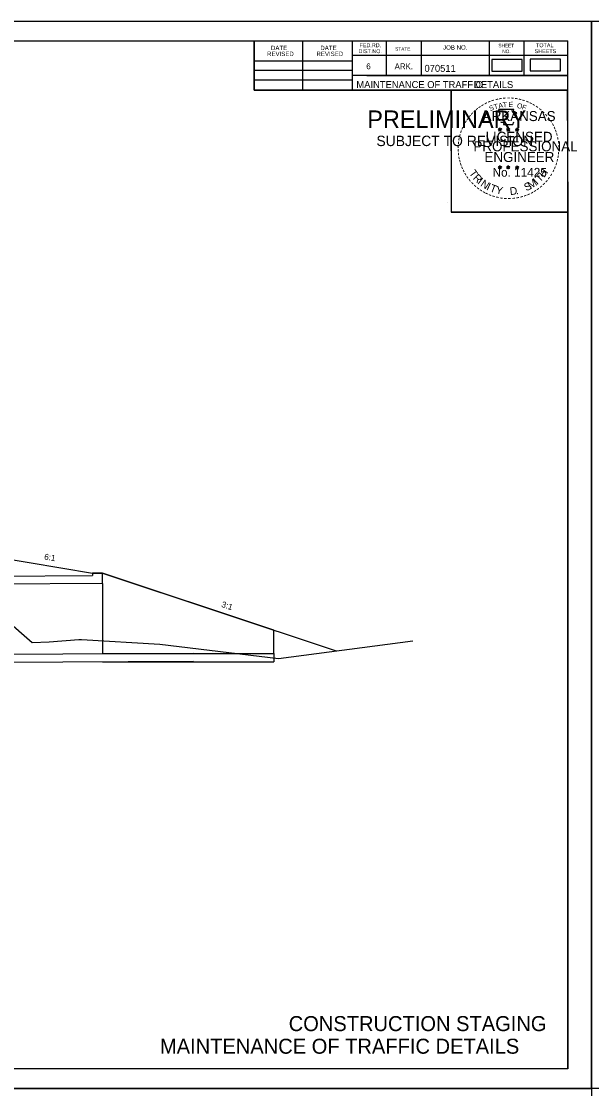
# Model space of a CAD drawing. Extents: x 1398460 to 1408037, y 380768 to 383968.
# Drawn here: x 1401763 to 1402332, y 382901 to 383968 of the extents above; entities that cross this region are included whole.
import ezdxf

# ---------------------------------------------------------------- set-up
doc = ezdxf.new("R2010")
doc.units = 0
for name, color, linetype in [('R_Border', 7, 'Continuous'), ('R_Border PE', 7, 'Continuous'), ('R_Border Prem', 7, 'Continuous'), ('R_Dimension', 7, 'Continuous'), ('R_Draft', 7, 'Continuous'), ('R_Exist Surface', 7, 'Continuous'), ('R_Fin Surface', 7, 'Continuous'), ('R_No Plot', 7, 'Continuous'), ('R_Water', 7, 'Continuous')]:
    doc.layers.add(name, color=color, linetype=linetype)

msp = doc.modelspace()

# ---------------------------------------------------------------- linework, layer by layer
at = {"layer": 'R_Border'}
for p, q in [((1400727.6, 383948.1), (1402308.5, 383948.1)), ((1401995.3, 383898.7), (1401995.3, 383948.1)), ((1402043.7, 383898.7), (1402043.7, 383948.1)), ((1402093, 383948.1), (1402093, 383898.7)), ((1402127.2, 383948.1), (1402127.2, 383913.4)), ((1402161.9, 383948.1), (1402161.9, 383913.4)), ((1402229.8, 383948.1), (1402229.8, 383913.4)), ((1402264.5, 383948.1), (1402264.5, 383913.4)), ((1402308.5, 382920.8), (1402308.5, 383948.1)), ((1402308.5, 383933.4), (1402093, 383933.4)), ((1402308.5, 383933.5), (1402308.5, 383933.5)), ((1401995.3, 383928), (1402093, 383928)), ((1401995.3, 383918.7), (1402093, 383918.7)), ((1402308.5, 383913.4), (1402093, 383913.4)), ((1402107.8, 383913.4), (1402308.5, 383913.4)), ((1401995.3, 383909), (1402093, 383909)), ((1402308.5, 383898.7), (1401995.3, 383898.7)), ((1402308.5, 382920.8), (1400727.6, 382920.8))]:
    msp.add_line(p, q, dxfattribs=at)
at = {"layer": 'R_Border PE'}
for p, q in [((1402238.9, 383860), (1402240.6, 383859.4)), ((1402238.9, 383860), (1402240.2, 383859.8)), ((1402238.9, 383860), (1402240.1, 383859.4)), ((1402239.6, 383857.9), (1402240.6, 383859.4)), ((1402239.6, 383857.9), (1402240.2, 383859.2)), ((1402239.6, 383857.9), (1402240.6, 383859)), ((1402240.6, 383861.3), (1402240.4, 383860)), ((1402240.6, 383859.4), (1402240.6, 383861.3)), ((1402240.6, 383861.3), (1402240.9, 383860)), ((1402242.4, 383860), (1402240.6, 383859.4)), ((1402241.7, 383857.9), (1402240.6, 383859.4)), ((1402241.7, 383857.9), (1402240.6, 383859)), ((1402242.4, 383860), (1402240.9, 383859.7)), ((1402241.7, 383857.9), (1402241, 383859.4)), ((1402242.4, 383860), (1402241.4, 383859.5)), ((1402247.2, 383860), (1402249, 383859.4)), ((1402247.2, 383860), (1402248.5, 383859.8)), ((1402247.2, 383860), (1402248.4, 383859.4)), ((1402247.9, 383857.9), (1402249, 383859.4)), ((1402247.9, 383857.9), (1402248.5, 383859.2)), ((1402247.9, 383857.9), (1402249, 383859)), ((1402249, 383861.3), (1402248.8, 383860)), ((1402249, 383859.4), (1402249, 383861.3)), ((1402249, 383861.3), (1402249.2, 383860)), ((1402250.7, 383860), (1402249, 383859.4)), ((1402250.1, 383857.9), (1402249, 383859.4)), ((1402250.1, 383857.9), (1402249, 383859)), ((1402250.7, 383860), (1402249.3, 383859.7)), ((1402250.1, 383857.9), (1402249.4, 383859.4)), ((1402250.7, 383860), (1402249.7, 383859.5)), ((1402256.1, 383859.9), (1402257.8, 383859.4)), ((1402256.1, 383859.9), (1402257.3, 383859.7)), ((1402256.1, 383859.9), (1402257.2, 383859.3)), ((1402256.7, 383857.9), (1402257.8, 383859.4)), ((1402256.7, 383857.9), (1402257.4, 383859.1)), ((1402256.7, 383857.9), (1402257.8, 383859)), ((1402257.8, 383861.2), (1402257.6, 383859.9)), ((1402257.8, 383859.4), (1402257.8, 383861.2)), ((1402257.8, 383861.2), (1402258.1, 383859.9)), ((1402259.5, 383859.9), (1402257.8, 383859.4)), ((1402258.9, 383857.9), (1402257.8, 383859.4)), ((1402258.9, 383857.9), (1402257.8, 383859)), ((1402259.5, 383859.9), (1402258.1, 383859.7)), ((1402258.9, 383857.9), (1402258.2, 383859.3)), ((1402259.5, 383859.9), (1402258.5, 383859.4)), ((1402238.9, 383822.1), (1402240.6, 383821.6)), ((1402238.9, 383822.1), (1402240.1, 383821.9)), ((1402238.9, 383822.1), (1402240.1, 383821.5)), ((1402239.5, 383820.1), (1402240.6, 383821.6)), ((1402239.5, 383820.1), (1402240.2, 383821.3)), ((1402239.5, 383820.1), (1402240.6, 383821.2)), ((1402240.6, 383823.4), (1402240.4, 383822.1)), ((1402240.6, 383821.6), (1402240.6, 383823.4)), ((1402240.6, 383823.4), (1402240.9, 383822.1)), ((1402242.4, 383822.1), (1402240.6, 383821.6)), ((1402241.7, 383820.1), (1402240.6, 383821.6)), ((1402241.7, 383820.1), (1402240.6, 383821.1)), ((1402242.4, 383822.1), (1402240.9, 383821.9)), ((1402241.7, 383820.1), (1402241, 383821.5)), ((1402242.4, 383822.1), (1402241.3, 383821.6)), ((1402247.2, 383822.1), (1402249, 383821.6)), ((1402247.2, 383822.1), (1402248.5, 383821.9)), ((1402247.2, 383822.1), (1402248.4, 383821.5)), ((1402247.9, 383820.1), (1402249, 383821.6)), ((1402247.9, 383820.1), (1402248.5, 383821.3)), ((1402247.9, 383820.1), (1402249, 383821.2)), ((1402249, 383823.4), (1402248.8, 383822.1)), ((1402249, 383821.6), (1402249, 383823.4)), ((1402249, 383823.4), (1402249.2, 383822.1)), ((1402250.7, 383822.1), (1402249, 383821.6)), ((1402250, 383820.1), (1402249, 383821.6)), ((1402250, 383820.1), (1402249, 383821.1)), ((1402250.7, 383822.1), (1402249.3, 383821.9)), ((1402250, 383820.1), (1402249.3, 383821.5)), ((1402250.7, 383822.1), (1402249.7, 383821.6)), ((1402256.1, 383822.1), (1402257.8, 383821.5)), ((1402256.1, 383822.1), (1402257.3, 383821.8)), ((1402256.1, 383822.1), (1402257.2, 383821.5)), ((1402256.7, 383820), (1402257.8, 383821.5)), ((1402256.7, 383820), (1402257.3, 383821.2)), ((1402256.7, 383820), (1402257.8, 383821.1)), ((1402257.8, 383823.3), (1402257.6, 383822.1)), ((1402257.8, 383821.5), (1402257.8, 383823.3)), ((1402257.8, 383823.3), (1402258, 383822.1)), ((1402259.5, 383822.1), (1402257.8, 383821.5)), ((1402258.9, 383820), (1402257.8, 383821.5)), ((1402258.9, 383820), (1402257.8, 383821.1)), ((1402259.5, 383822.1), (1402258.1, 383821.8)), ((1402258.9, 383820), (1402258.2, 383821.5)), ((1402259.5, 383822.1), (1402258.5, 383821.6))]:
    msp.add_line(p, q, dxfattribs=at)
for points in [[(1402239.1, 383879.4), (1402240.4, 383875.2)], [(1402256.7, 383874.8), (1402257.4, 383876.2), (1402253.9, 383876.1), (1402254.7, 383879.4), (1402239.1, 383879.4)], [(1402240.6, 383861.3), (1402241.7, 383857.9), (1402238.9, 383860), (1402242.4, 383860), (1402239.6, 383857.9), (1402240.6, 383861.3)], [(1402241.6, 383867.3), (1402241.6, 383866.8), (1402244.4, 383866.7), (1402244.1, 383864.4), (1402253.5, 383864.4), (1402254.5, 383867)], [(1402249, 383861.3), (1402250.1, 383857.9), (1402247.2, 383860), (1402250.7, 383860), (1402247.9, 383857.9), (1402249, 383861.3)], [(1402257.8, 383861.2), (1402258.9, 383857.9), (1402256.1, 383859.9), (1402259.5, 383859.9), (1402256.7, 383857.9), (1402257.8, 383861.2)], [(1402240.6, 383823.4), (1402241.7, 383820.1), (1402238.9, 383822.1), (1402242.4, 383822.1), (1402239.5, 383820.1), (1402240.6, 383823.4)], [(1402249, 383823.4), (1402250, 383820.1), (1402247.2, 383822.1), (1402250.7, 383822.1), (1402247.9, 383820.1), (1402249, 383823.4)], [(1402257.8, 383823.3), (1402258.9, 383820), (1402256.1, 383822.1), (1402259.5, 383822.1), (1402256.7, 383820), (1402257.8, 383823.3)]]:
    msp.add_lwpolyline(points, dxfattribs=at)
for centre, radius in [((1402240.6, 383859.4), 0.861), ((1402240.6, 383859.4), 0.723), ((1402240.6, 383859.4), 0.579), ((1402240.6, 383859.4), 0.495), ((1402240.6, 383859.4), 0.374), ((1402240.6, 383859.4), 0.248), ((1402240.6, 383859.4), 0.148), ((1402249, 383859.4), 0.861), ((1402249, 383859.4), 0.723), ((1402249, 383859.4), 0.579), ((1402249, 383859.4), 0.495), ((1402249, 383859.4), 0.374), ((1402249, 383859.4), 0.248), ((1402249, 383859.4), 0.148), ((1402257.8, 383859.4), 0.861), ((1402257.8, 383859.4), 0.723), ((1402257.8, 383859.4), 0.579), ((1402257.8, 383859.4), 0.495), ((1402257.8, 383859.4), 0.374), ((1402257.8, 383859.4), 0.248), ((1402257.8, 383859.4), 0.148), ((1402240.6, 383821.6), 0.861), ((1402240.6, 383821.6), 0.723), ((1402240.6, 383821.6), 0.579), ((1402240.6, 383821.6), 0.495), ((1402240.6, 383821.6), 0.374), ((1402240.6, 383821.6), 0.248), ((1402240.6, 383821.6), 0.148), ((1402249, 383821.6), 0.861), ((1402249, 383821.6), 0.723), ((1402249, 383821.6), 0.579), ((1402249, 383821.6), 0.495), ((1402249, 383821.6), 0.374), ((1402249, 383821.6), 0.248), ((1402249, 383821.6), 0.148), ((1402257.8, 383821.5), 0.861), ((1402257.8, 383821.5), 0.723), ((1402257.8, 383821.5), 0.579), ((1402257.8, 383821.5), 0.495), ((1402257.8, 383821.5), 0.374), ((1402257.8, 383821.5), 0.248), ((1402257.8, 383821.5), 0.148)]:
    msp.add_circle(centre, radius, dxfattribs=at)
at = {"layer": 'R_Dimension'}
for points in [[(1402232.5, 383917.7), (1402262.7, 383917.7), (1402262.7, 383929.3), (1402232.5, 383929.3)], [(1402270.8, 383918.2), (1402301.1, 383918.2), (1402301.1, 383929.8), (1402270.8, 383929.8)]]:
    msp.add_lwpolyline(points, close=True, dxfattribs=at)
at = {"layer": 'R_Exist Surface'}
msp.add_lwpolyline([(1401687, 383422.3), (1401773.4, 383346.7), (1401790.6, 383347.4), (1401820.1, 383349.8), (1401822.6, 383349.9), (1401901, 383345.2), (1402019.4, 383330.7), (1402153.8, 383348.6)], dxfattribs=at)
at = {"layer": 'R_Fin Surface'}
msp.add_line((1401678.9, 383442), (1401833.6, 383416.2), dxfattribs=at)
msp.add_lwpolyline([(1401833.6, 383416.2), (1401843.6, 383416.2), (1402077, 383338.4)], dxfattribs=at)
at = {"layer": 'R_No Plot'}
for p, q in [((1400665.6, 383967.6), (1402332.2, 383967.6)), ((1402188.6, 383786.4), (1402188.6, 383786.4)), ((1400665.6, 382900.9), (1402332.2, 382900.9)), ((1400665.6, 382900.9), (1402332.2, 382900.9))]:
    msp.add_line(p, q, dxfattribs=at)
for points in [[(1400665.5, 383967.6), (1402332.2, 383967.6), (1402332.2, 382900.9), (1400665.5, 382900.9)], [(1402332.2, 383967.6), (1403998.9, 383967.6), (1403998.9, 382900.9), (1402332.2, 382900.9)], [(1401897.2, 383948.1), (1401995.3, 383948.1), (1401995.3, 383898.7), (1402075.8, 383898.7), (1402191.8, 383898.7), (1402191.8, 383777), (1402308.5, 383777), (1402308.5, 382920.8), (1400727.6, 382920.8), (1400727.6, 383948.1)], [(1402191.8, 383898.7), (1402307.9, 383898.7), (1402308.5, 383777), (1402192.4, 383777)], [(1400665.5, 382900.9), (1402332.2, 382900.9), (1402332.2, 381834.2), (1400665.5, 381834.2)]]:
    msp.add_lwpolyline(points, close=True, dxfattribs=at)
at = {"layer": 'R_Water'}
for p, q in [((1401498.9, 383412), (1401833.6, 383413.6)), ((1402014.9, 383359.1), (1401843.6, 383416.2)), ((1401843.6, 383405.6), (1401498.9, 383404)), ((1401843.6, 383405.8), (1401843.6, 383335.8)), ((1402014.9, 383335.8), (1402014.9, 383359.1)), ((1401498.9, 383334), (1401934.7, 383336.1)), ((1401843.6, 383335.8), (1402014.9, 383335.8)), ((1402014.9, 383335.8), (1402014.9, 383327.4)), ((1401934.7, 383327.7), (1401498.9, 383325.7)), ((1401843.6, 383327.4), (1402014.9, 383327.4))]:
    msp.add_line(p, q, dxfattribs=at)
msp.add_lwpolyline([(1401843.6, 383405.8), (1401843.6, 383416.2), (1401833.6, 383416.2), (1401833.6, 383413.7)], dxfattribs=at)

# ---------------------------------------------------------------- texts
at = {"layer": 'R_Border'}
for s, height, p in [('FED.RD.', 3.91, (1402100.4, 383941.7)), ('JOB NO.', 4.4, (1402183.9, 383939.3)), ('SHEET', 3.42, (1402239.1, 383941.7)), ('TOTAL', 3.91, (1402276.7, 383941.7)), ('REVISED', 4.4, (1402008.1, 383932.9)), ('DATE', 4.4, (1402012, 383938.8)), ('REVISED', 4.4, (1402057.4, 383932.9)), ('DATE', 4.4, (1402061.3, 383938.8)), ('DIST.NO.', 3.91, (1402099.4, 383935.8)), ('STATE', 3.42, (1402136, 383938.3)), ('NO.', 3.42, (1402243, 383935.8)), ('SHEETS', 3.91, (1402275.3, 383935.8)), ('6', 5.86, (1402107.2, 383919.7)), ('ARK.', 5.86, (1402135.5, 383919.7)), ('070511', 7, (1402165.3, 383917.1)), ('MAINTENANCE OF TRAFFIC', 7, (1402097.3, 383900.9)), (' DETAILS', 7, (1402212.3, 383900.9)), ('CONSTRUCTION STAGING', 15, (1402029.7, 382958.4)), ('MAINTENANCE OF TRAFFIC DETAILS', 15, (1401901.1, 382935.8))]:
    msp.add_text(s, height=height, dxfattribs=at).set_placement(p)
at = {"layer": 'R_Border PE'}
for s, height, rotation, p in [('-', 8, 13.6302, (1402236.6, 383886.2)), ('-', 8, 10.2193, (1402240, 383887)), ('-', 8, 5.8968, (1402243.6, 383887.6)), ('-', 8, 0.1862, (1402247.5, 383887.9)), ('-', 8, 357.743, (1402251.1, 383887.9)), ('-', 8, 352.1617, (1402254.8, 383887.6)), ('-', 8, 347.2049, (1402258.4, 383887)), ('-', 8, 38.9507, (1402218.2, 383876.4)), ('-', 8, 36.2317, (1402220.6, 383878.3)), ('-', 8, 34.0636, (1402223.5, 383880.2)), ('-', 8, 28.7918, (1402226.5, 383882.1)), ('-', 8, 24.3072, (1402229.7, 383883.7)), ('S', 5, 21.594, (1402230.9, 383877.8)), ('-', 8, 19.1761, (1402232.8, 383885)), ('T', 5, 16.4036, (1402235.4, 383879.4)), ('A', 5, 11.2132, (1402239.6, 383880.7)), ('T', 5, 6.0228, (1402243.8, 383881.5)), ('E', 5, 0.8323, (1402249.3, 383882.1)), ('O', 5, 350.4515, (1402257.4, 383881)), ('F', 5, 340.0707, (1402262.1, 383879.9)), ('-', 8, 342.3362, (1402261.6, 383886.2)), ('-', 8, 337.8551, (1402265.3, 383885.1)), ('-', 8, 334.1211, (1402268.4, 383883.8)), ('-', 8, 329.6409, (1402271.3, 383882.4)), ('-', 8, 325.8627, (1402274.5, 383880.6)), ('-', 8, 320.5297, (1402277.6, 383878.4)), ('-', 8, 54.2325, (1402209.8, 383866.6)), ('-', 8, 50.6142, (1402211.8, 383869.5)), ('-', 8, 48.4231, (1402213.8, 383871.9)), ('-', 8, 42.9622, (1402216.1, 383874.3)), ('-', 8, 315.5786, (1402280.6, 383876)), ('-', 8, 309.8797, (1402283.4, 383873.2)), ('-', 8, 306.6522, (1402286, 383870.2)), ('-', 8, 72.3945, (1402204.2, 383854.7)), ('-', 8, 67.7743, (1402205.3, 383857.9)), ('-', 8, 62.8713, (1402206.6, 383860.9)), ('-', 8, 58.0706, (1402208.1, 383864)), ('-', 7, 303.6753, (1402288.5, 383867.4)), ('-', 8, 299.6684, (1402290.1, 383864.3)), ('-', 8, 294.6628, (1402291.7, 383861.3)), ('-', 8, 290.5728, (1402293, 383858.4)), ('-', 8, 81.2013, (1402202.5, 383847.6)), ('-', 8, 75.461, (1402203.2, 383851.1)), ('-', 8, 285.1233, (1402294.1, 383855.5)), ('-', 8, 280.5493, (1402295.1, 383851.8)), ('-', 8, 276.5962, (1402296, 383848)), ('-', 8, 94.1959, (1402202.2, 383837)), ('-', 8, 89.0622, (1402202, 383840.6)), ('-', 8, 85.1863, (1402202.2, 383844.1)), ('-', 8, 263.5172, (1402296.3, 383837.9)), ('-', 8, 274.3301, (1402296.3, 383844.3)), ('-', 8, 269.9407, (1402296.4, 383841.2)), ('-', 8, 98.9479, (1402202.6, 383833.7)), ('-', 8, 101.7149, (1402203.2, 383830)), ('-', 8, 105.4578, (1402204.1, 383827)), ('-', 8, 252.8681, (1402294.5, 383827.6)), ('-', 8, 255.7626, (1402295.4, 383831.2)), ('-', 8, 260.9953, (1402296, 383834.6)), ('-', 8, 109.0874, (1402205.1, 383823.9)), ('-', 8, 114.0643, (1402206.4, 383820.9)), ('-', 8, 115.7289, (1402207.9, 383817.8)), ('-', 8, 120.4471, (1402209.7, 383814.9)), ('T', 7.7, 306.0406, (1402209.4, 383815.8)), ('T', 7.7, 46.6444, (1402280.6, 383806.2)), ('H', 7.7, 54.6088, (1402285, 383810.9)), ('-', 8, 244.6197, (1402292.1, 383821.1)), ('-', 8, 247.8887, (1402293.4, 383824.2)), ('-', 8, 125.8934, (1402211.7, 383812.1)), ('-', 8, 130.7181, (1402214, 383809.3)), ('-', 8, 134.2238, (1402216.6, 383806.6)), ('R', 7.7, 314.005, (1402213.2, 383810.5)), ('I', 7.7, 321.9694, (1402217.7, 383805.9)), ('N', 7.7, 326.5002, (1402220.6, 383803.5)), ('I', 7.7, 335.3603, (1402226.6, 383799.6)), ('T', 7.7, 339.8912, (1402229.9, 383797.9)), ('S', 7.7, 26.9312, (1402267.1, 383797.6)), ('M', 7.7, 32.6563, (1402271.3, 383799.6)), ('I', 7.7, 42.1136, (1402277.8, 383803.8)), ('-', 8, 225.7653, (1402283.6, 383808.4)), ('-', 8, 231.2538, (1402286, 383811.2)), ('-', 8, 233.8452, (1402288.1, 383814.1)), ('-', 8, 239.0712, (1402290.1, 383817.3)), ('-', 8, 138.9338, (1402219.2, 383804.3)), ('-', 8, 144.6463, (1402222, 383802.2)), ('-', 8, 148.0898, (1402224.8, 383800.4)), ('-', 8, 151.5704, (1402227.7, 383798.7)), ('-', 8, 154.6002, (1402230.3, 383797.5)), ('-', 8, 158.5612, (1402233.5, 383796.2)), ('Y', 7.7, 347.8556, (1402236, 383795.7)), ('D', 7.7, 6.3969, (1402250.9, 383793.9)), ('.', 7.7, 13.7642, (1402256.9, 383794.5)), ('-', 8, 204.2516, (1402269.6, 383798.2)), ('-', 8, 207.3568, (1402272.8, 383799.8)), ('-', 8, 212.2491, (1402275.5, 383801.6)), ('-', 8, 215.7363, (1402278.2, 383803.5)), ('-', 8, 221.0851, (1402281, 383805.9)), ('-', 8, 162.7983, (1402236.9, 383795.2)), ('-', 8, 167.5555, (1402240.5, 383794.4)), ('-', 8, 173.1155, (1402244.3, 383793.8)), ('-', 8, 176.5183, (1402248.1, 383793.5)), ('-', 8, 181.5918, (1402251.8, 383793.6)), ('-', 8, 185.8167, (1402255.8, 383794)), ('-', 8, 191.2858, (1402259.5, 383794.7)), ('-', 8, 195.4743, (1402263.2, 383795.7)), ('-', 8, 200.7184, (1402266.5, 383796.9))]:
    msp.add_text(s, height=height, rotation=rotation, dxfattribs=at).set_placement(p)
for s, height, p in [('ARKANSAS', 10, (1402223.4, 383867.9)), ('DWB', 0.05, (1402240.6, 383859.4)), ('DWB', 0.05, (1402248.9, 383859.4)), ('DWB', 0.05, (1402257.7, 383859.3)), ('PROFESSIONAL', 10, (1402214.2, 383837.7)), ('LICENSED', 10, (1402226.3, 383847.2)), ('ENGINEER', 10, (1402225.2, 383827)), ('No. 11425', 8.78, (1402233.3, 383812.3)), ('DWB', 0.05, (1402240.6, 383821.5)), ('DWB', 0.05, (1402248.9, 383821.5)), ('DWB', 0.05, (1402257.7, 383821.5))]:
    msp.add_text(s, height=height, dxfattribs=at).set_placement(p)
at = {"layer": 'R_Border Prem'}
for s, height, p in [('PRELIMINARY', 17.5, (1402108.2, 383861)), ('DWB', 0.05, (1402112, 383870.3)), ('SUBJECT TO REVISION', 10.376, (1402117.3, 383842.9))]:
    msp.add_text(s, height=height, dxfattribs=at).set_placement(p)
at = {"layer": 'R_Draft'}
for s, rotation, p in [('6:1', 350.5377, (1401785.2, 383429.8)), ('3:1', 341.5652, (1401962, 383382.5))]:
    msp.add_text(s, height=6, rotation=rotation, dxfattribs=at).set_placement(p)

doc.saveas('drawing.dxf')
